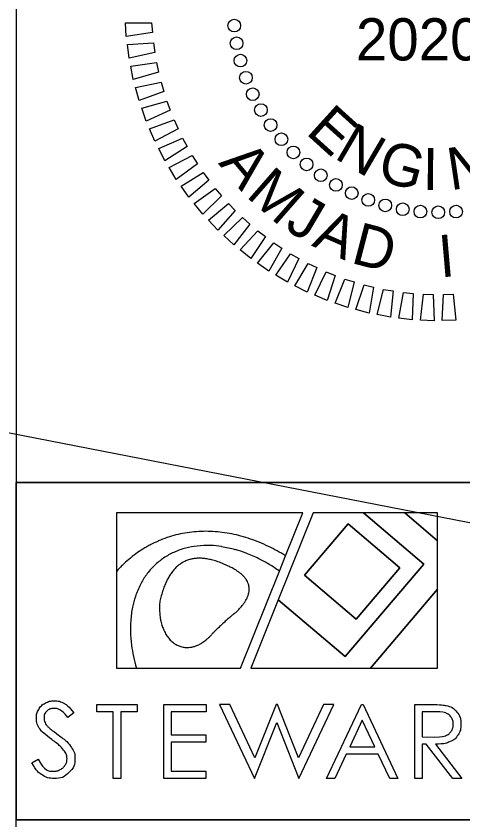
# Model space of a CAD drawing. Extents: x 1632447 to 1634147, y 883210 to 885181.
# Drawn here: x 1633913.8 to 1633966.7, y 884795.1 to 884890.3 of the extents above; entities that cross this region are included whole.
import ezdxf

# ---------------------------------------------------------------- set-up
doc = ezdxf.new("R2010")
doc.units = 0
for name, color, linetype in [('Default', 7, 'Continuous'), ('Scratch_Level_8', 7, 'Continuous'), ('Sheet PE Seal Cell', 7, 'Continuous'), ('Sheet Plan And Profile CELL', 7, 'Continuous'), ('Sheet Profile CELL', 7, 'Continuous')]:
    doc.layers.add(name, color=color, linetype=linetype)

msp = doc.modelspace()

# ---------------------------------------------------------------- linework, layer by layer
at = {"layer": 'Default'}
for p, q in [((1633947.786, 884831.455), (1633925.711, 884831.455)), ((1633925.711, 884831.455), (1633925.711, 884824.503)), ((1633949.016, 884831.455), (1633944.869, 884821.141)), ((1633945.732, 884826.348), (1633947.786, 884831.455)), ((1633954.969, 884831.455), (1633949.016, 884831.455)), ((1633954.969, 884831.455), (1633962.12, 884825.364)), ((1633959.863, 884831.455), (1633954.969, 884831.455)), ((1633962.12, 884825.364), (1633954.969, 884831.455)), ((1633963.748, 884831.455), (1633959.863, 884831.455)), ((1633959.863, 884831.455), (1633963.748, 884828.146)), ((1633963.748, 884828.146), (1633959.863, 884831.455)), ((1633963.748, 884828.146), (1633963.748, 884831.455)), ((1633931.724, 884828.517), (1633931.68, 884828.504)), ((1633938.234, 884829.128), (1633938.243, 884829.127)), ((1633930.659, 884828.114), (1633930.632, 884828.085)), ((1633938.146, 884827.422), (1633938.188, 884827.443)), ((1633943.718, 884827.467), (1633943.724, 884827.464)), ((1633963.748, 884822.381), (1633963.748, 884828.146)), ((1633945.004, 884824.537), (1633945.732, 884826.348)), ((1633925.711, 884824.503), (1633925.711, 884813.052)), ((1633940.386, 884813.052), (1633945.004, 884824.537)), ((1633962.12, 884825.364), (1633952.782, 884814.401)), ((1633952.782, 884814.401), (1633962.12, 884825.364)), ((1633954.102, 884818.861), (1633959.286, 884824.946)), ((1633963.748, 884822.381), (1633955.802, 884813.052)), ((1633955.802, 884813.052), (1633963.748, 884822.381)), ((1633963.748, 884813.052), (1633963.748, 884822.381)), ((1633944.869, 884821.141), (1633941.616, 884813.052)), ((1633952.782, 884814.401), (1633944.869, 884821.141)), ((1633944.869, 884821.141), (1633952.782, 884814.401)), ((1633925.711, 884813.052), (1633928.086, 884813.052)), ((1633928.086, 884813.052), (1633940.386, 884813.052)), ((1633941.616, 884813.052), (1633955.802, 884813.052)), ((1633955.802, 884813.052), (1633963.748, 884813.052)), ((1633939.126, 884808.723), (1633937.933, 884808.723)), ((1633937.933, 884808.723), (1633942.051, 884799.973)), ((1633942.102, 884802.417), (1633939.126, 884808.723)), ((1633944.626, 884808.723), (1633942.102, 884802.417)), ((1633944.796, 884808.723), (1633944.626, 884808.723)), ((1633947.275, 884802.417), (1633944.796, 884808.723)), ((1633950.251, 884808.723), (1633947.275, 884802.417)), ((1633947.313, 884799.973), (1633951.444, 884808.723)), ((1633951.444, 884808.723), (1633950.251, 884808.723)), ((1633942.051, 884799.973), (1633944.71, 884806.598)), ((1633944.71, 884806.598), (1633947.313, 884799.973)), ((1633913.826, 884771.558), (1633913.826, 884795.058)), ((1633913.826, 884795.058), (1634113.863, 884795.058)), ((1633913.826, 884771.558), (1633913.826, 884795.058)), ((1633913.826, 884795.058), (1634113.863, 884795.058))]:
    msp.add_line(p, q, dxfattribs=at)
for points in [[(1633913.813, 884835.058), (1634013.813, 884835.058), (1634013.813, 884795.058), (1633913.813, 884795.058)], [(1634013.813, 884835.058), (1633913.813, 884835.058), (1633913.813, 884795.058), (1634013.813, 884795.058)]]:
    msp.add_lwpolyline(points, close=True, dxfattribs=at)
for points in [[(1633947.991, 884824.066), (1633953.174, 884830.152), (1633959.286, 884824.946), (1633954.102, 884818.861), (1633947.991, 884824.066)], [(1633959.286, 884824.946), (1633953.174, 884830.152), (1633947.991, 884824.066), (1633954.102, 884818.861)], [(1633929.699, 884827.643), (1633929.775, 884827.686)], [(1633939.819, 884827.089), (1633939.775, 884827.068)], [(1633926.418, 884825.229), (1633926.358, 884825.187)], [(1633939.384, 884819.279), (1633939.264, 884819.179)], [(1633939.566, 884819.421), (1633939.486, 884819.36)], [(1633939.696, 884819.501), (1633939.626, 884819.463)], [(1633937.185, 884817.235), (1633937.085, 884817.132)], [(1633923.369, 884807.866), (1633923.369, 884808.723), (1633928.158, 884808.723), (1633928.158, 884807.866), (1633926.21, 884807.866), (1633926.21, 884799.973), (1633925.317, 884799.973), (1633925.317, 884807.866), (1633923.369, 884807.866)], [(1633931.325, 884808.723), (1633936.341, 884808.723), (1633936.341, 884807.866), (1633932.197, 884807.866), (1633932.197, 884805.124), (1633936.306, 884805.124), (1633936.306, 884804.267), (1633932.197, 884804.267), (1633932.197, 884800.83), (1633936.306, 884800.83), (1633936.306, 884799.973), (1633931.325, 884799.973), (1633931.325, 884808.723)], [(1633954.946, 884808.723), (1633959.027, 884799.973), (1633958.082, 884799.973), (1633956.708, 884802.857), (1633952.939, 884802.857), (1633951.578, 884799.973), (1633950.603, 884799.973), (1633954.734, 884808.723), (1633954.946, 884808.723)], [(1633961.041, 884808.723), (1633962.781, 884808.723)], [(1633963.488, 884804.033), (1633966.631, 884799.973), (1633965.549, 884799.973), (1633962.405, 884804.033), (1633961.913, 884804.033), (1633961.913, 884799.973), (1633961.041, 884799.973), (1633961.041, 884808.723)], [(1633920.645, 884807.727), (1633919.931, 884807.186)], [(1633961.913, 884807.866), (1633961.913, 884804.89), (1633963.419, 884804.878)], [(1633963.455, 884807.866), (1633961.913, 884807.866)], [(1633954.834, 884806.87), (1633953.337, 884803.7), (1633956.327, 884803.7), (1633954.834, 884806.87)], [(1633915.678, 884801.823), (1633916.422, 884802.269)]]:
    msp.add_lwpolyline(points, dxfattribs=at)
for centre, radius, start, end in [((1633936.259, 884814.687), 14.566, 91.0141, 95.33896), ((1633936.259, 884814.687), 14.566, 91.0141, 95.33896), ((1633936.275, 884813.805), 15.448, 86.81452, 91.0141), ((1633936.275, 884813.805), 15.448, 86.81452, 91.0141), ((1633936.203, 884815.137), 14.111, 108.6948, 113.13309), ((1633936.203, 884815.137), 14.111, 108.6948, 113.13309), ((1633936.06, 884815.704), 13.527, 104.17801, 108.6948), ((1633936.06, 884815.704), 13.527, 104.17801, 108.6948), ((1633936.203, 884815.137), 14.111, 99.74382, 104.17801), ((1633936.203, 884815.137), 14.111, 99.74382, 104.17801), ((1633936.235, 884814.952), 14.3, 95.33896, 99.74382), ((1633936.235, 884814.952), 14.3, 95.33896, 99.74382), ((1633936.275, 884813.805), 15.448, 82.68224, 86.81452), ((1633936.275, 884813.805), 15.448, 82.68224, 86.81452), ((1633936.078, 884812.334), 16.932, 78.75005, 82.68224), ((1633936.078, 884812.334), 16.932, 78.75005, 82.68224), ((1633936.192, 884812.909), 16.346, 74.86342, 78.75005), ((1633936.192, 884812.909), 16.346, 74.86342, 78.75005), ((1633935.582, 884810.654), 18.681, 71.22794, 74.86342), ((1633935.582, 884810.654), 18.681, 71.22794, 74.86342), ((1633935.955, 884811.751), 17.523, 67.61084, 71.22794), ((1633935.955, 884811.751), 17.523, 67.61084, 71.22794), ((1633936.399, 884815.042), 14.274, 117.64902, 121.98098), ((1633936.399, 884815.042), 14.274, 117.64902, 121.98098), ((1633935.782, 884816.031), 13.108, 113.13309, 117.64902), ((1633935.782, 884816.031), 13.108, 113.13309, 117.64902), ((1633936.154, 884818.904), 8.654, 95.97029, 104.98979), ((1633936.154, 884818.904), 8.654, 95.97029, 104.98979), ((1633936.498, 884815.62), 11.957, 88.29908, 95.97029), ((1633936.498, 884815.62), 11.957, 88.29908, 95.97029), ((1633936.549, 884817.368), 10.207, 80.76366, 88.29908), ((1633936.549, 884817.368), 10.207, 80.76366, 88.29908), ((1633935.612, 884811.838), 15.789, 74.71033, 80.76366), ((1633935.612, 884811.838), 15.789, 74.71033, 80.76366), ((1633934.784, 884808.909), 20.597, 64.27468, 67.61084), ((1633934.784, 884808.909), 20.597, 64.27468, 67.61084), ((1633935.138, 884809.66), 19.767, 60.92836, 64.27468), ((1633935.138, 884809.66), 19.767, 60.92836, 64.27468), ((1633936.843, 884814.591), 14.897, 126.38314, 130.51246), ((1633936.843, 884814.591), 14.897, 126.38314, 130.51246), ((1633935.782, 884816.031), 13.108, 121.98098, 126.38314), ((1633935.782, 884816.031), 13.108, 121.98098, 126.38314), ((1633935.825, 884819.411), 8.064, 114.2575, 124.17212), ((1633935.825, 884819.411), 8.064, 114.2575, 124.17212), ((1633936.302, 884818.352), 9.226, 104.98979, 114.2575), ((1633936.302, 884818.352), 9.226, 104.98979, 114.2575), ((1633936.604, 884815.327), 12.193, 68.58238, 74.71033), ((1633936.604, 884815.327), 12.193, 68.58238, 74.71033), ((1633933.756, 884808.066), 19.993, 63.79776, 68.58238), ((1633933.756, 884808.066), 19.993, 63.79776, 68.58238), ((1633935.138, 884809.66), 19.767, 57.5922, 60.92836), ((1633935.138, 884809.66), 19.767, 57.5922, 60.92836), ((1633936.183, 884815.363), 13.881, 130.51246, 134.70691), ((1633936.183, 884815.363), 13.881, 130.51246, 134.70691), ((1633935.78, 884819.477), 7.985, 124.17212, 134.18211), ((1633935.78, 884819.477), 7.985, 124.17212, 134.18211), ((1633935.409, 884822.325), 3.73, 119.02596, 126.10024), ((1633935.409, 884822.325), 3.73, 119.02596, 126.10024), ((1633935.377, 884822.382), 3.664, 111.82778, 119.02597), ((1633935.377, 884822.382), 3.664, 111.82778, 119.02597), ((1633935.415, 884822.287), 3.767, 104.72849, 111.82778), ((1633935.415, 884822.287), 3.767, 104.72849, 111.82778), ((1633935.45, 884822.157), 3.901, 97.90175, 104.7285), ((1633935.45, 884822.157), 3.901, 97.90175, 104.7285), ((1633935.531, 884821.573), 4.492, 91.53976, 97.90175), ((1633935.531, 884821.573), 4.492, 91.53976, 97.90175), ((1633935.54, 884821.227), 4.838, 85.68251, 91.53976), ((1633935.54, 884821.227), 4.838, 85.68251, 91.53976), ((1633935.452, 884820.06), 6.008, 80.42702, 85.68251), ((1633935.452, 884820.06), 6.008, 80.42702, 85.68251), ((1633935.356, 884819.488), 6.587, 75.69708, 80.42702), ((1633935.356, 884819.488), 6.587, 75.69708, 80.42702), ((1633934.887, 884817.652), 8.483, 71.52919, 75.69708), ((1633934.887, 884817.652), 8.483, 71.52919, 75.69708), ((1633934.243, 884815.724), 10.516, 67.79994, 71.52919), ((1633934.243, 884815.724), 10.516, 67.79994, 71.52919), ((1633935.035, 884817.664), 8.419, 63.63204, 67.79994), ((1633935.035, 884817.664), 8.419, 63.63204, 67.79994), ((1633935.612, 884811.838), 15.789, 58.77838, 63.79776), ((1633935.612, 884811.838), 15.789, 58.77838, 63.79776), ((1633936.399, 884815.042), 14.274, 134.70691, 138.48502), ((1633936.399, 884815.042), 14.274, 134.70691, 138.48502), ((1633936.363, 884818.877), 8.821, 134.18211, 143.7045), ((1633936.363, 884818.877), 8.821, 134.18211, 143.7045), ((1633936.491, 884821.24), 5.269, 139.15431, 144.89501), ((1633936.491, 884821.24), 5.269, 139.15431, 144.89501), ((1633935.811, 884821.829), 4.37, 132.84964, 139.15431), ((1633935.811, 884821.829), 4.37, 132.84964, 139.15431), ((1633935.625, 884822.029), 4.097, 126.10024, 132.84964), ((1633935.625, 884822.029), 4.097, 126.10024, 132.84964), ((1633936.28, 884819.098), 6.6, 63.90222, 67.78989), ((1633936.28, 884819.098), 6.6, 63.90222, 67.78989), ((1633935.372, 884817.245), 8.663, 60.50912, 63.90221), ((1633935.372, 884817.245), 8.663, 60.50912, 63.90221), ((1633936.356, 884818.985), 6.664, 56.62145, 60.50912), ((1633936.356, 884818.985), 6.664, 56.62145, 60.50912), ((1633937.341, 884820.479), 4.875, 52.07574, 56.62144), ((1633937.341, 884820.479), 4.875, 52.07574, 56.62144), ((1633934.79, 884810.481), 17.375, 53.99375, 58.77838), ((1633934.79, 884810.481), 17.375, 53.99375, 58.77838), ((1633935.827, 884819.27), 8.157, 143.7045, 153.10241), ((1633935.827, 884819.27), 8.157, 143.7045, 153.10241), ((1633938.254, 884820.174), 7.331, 150.09139, 154.70217), ((1633938.254, 884820.174), 7.331, 150.09139, 154.70217), ((1633936.903, 884820.951), 5.772, 144.89501, 150.09139), ((1633936.903, 884820.951), 5.772, 144.89501, 150.09139), ((1633937.699, 884820.939), 4.292, 46.84444, 52.07574), ((1633937.699, 884820.939), 4.292, 46.84444, 52.07574), ((1633938.452, 884821.742), 3.191, 40.77679, 46.84444), ((1633938.452, 884821.742), 3.191, 40.77679, 46.84444), ((1633938.721, 884821.974), 2.835, 33.89614, 40.77679), ((1633938.721, 884821.974), 2.835, 33.89614, 40.77679), ((1633939.199, 884822.295), 2.26, 26.18824, 33.89614), ((1633939.199, 884822.295), 2.26, 26.18824, 33.89614), ((1633938.421, 884817.954), 11.065, 153.10241, 161.16886), ((1633938.421, 884817.954), 11.065, 153.10241, 161.16886), ((1633941.157, 884818.991), 10.467, 158.82578, 162.45014), ((1633941.157, 884818.991), 10.467, 158.82578, 162.45014), ((1633938.937, 884819.851), 8.087, 154.70217, 158.82578), ((1633938.937, 884819.851), 8.087, 154.70217, 158.82578), ((1633939.344, 884822.367), 2.098, 17.85938, 26.18823), ((1633939.344, 884822.367), 2.098, 17.85938, 26.18823), ((1633939.506, 884822.419), 1.928, 9.17109, 17.85938), ((1633939.506, 884822.419), 1.928, 9.17109, 17.85938), ((1633939.5, 884822.418), 1.934, 0.50696, 9.17108), ((1633939.5, 884822.418), 1.934, 0.50696, 9.17108), ((1633943.529, 884818.241), 12.955, 162.45014, 165.69373), ((1633943.529, 884818.241), 12.955, 162.45014, 165.69373), ((1633938.554, 884822.599), 2.904, 337.85452, 344.63043), ((1633938.554, 884822.599), 2.904, 337.85452, 344.63043), ((1633939.135, 884822.439), 2.3, 344.63043, 352.24439), ((1633939.135, 884822.439), 2.3, 344.63043, 352.24439), ((1633939.308, 884822.416), 2.126, 352.24438, 0.50695), ((1633939.308, 884822.416), 2.126, 352.24438, 0.50695), ((1633936.85, 884818.49), 9.405, 161.16886, 169.12791), ((1633936.85, 884818.49), 9.405, 161.16886, 169.12791), ((1633938.393, 884820.135), 7.589, 174.9583, 179.11247), ((1633938.393, 884820.135), 7.589, 174.9583, 179.11247), ((1633941.03, 884818.878), 10.376, 165.69373, 169.31809), ((1633941.03, 884818.878), 10.376, 165.69373, 169.31809), ((1633936.705, 884823.604), 5.012, 322.29152, 326.75387), ((1633936.705, 884823.604), 5.012, 322.29152, 326.75387), ((1633937.207, 884823.275), 4.412, 326.75387, 331.89068), ((1633937.207, 884823.275), 4.412, 326.75387, 331.89068), ((1633938.211, 884822.739), 3.274, 331.89068, 337.85452), ((1633938.211, 884822.739), 3.274, 331.89068, 337.85452), ((1633941.9, 884817.52), 14.548, 169.1279, 175.52553), ((1633941.9, 884817.52), 14.548, 169.1279, 175.52553), ((1633937.586, 884820.147), 6.781, 179.11246, 183.50718), ((1633937.586, 884820.147), 6.781, 179.11246, 183.50718), ((1633939.551, 884820.268), 8.75, 183.50718, 187.66135), ((1633939.551, 884820.268), 8.75, 183.50718, 187.66135), ((1633935.218, 884824.594), 6.782, 311.32427, 315.14136), ((1633935.218, 884824.594), 6.782, 311.32427, 315.14136), ((1633933.72, 884826.084), 8.894, 315.14136, 318.47442), ((1633933.72, 884826.084), 8.894, 315.14136, 318.47442), ((1633935.252, 884824.728), 6.849, 318.47442, 322.29152), ((1633935.252, 884824.728), 6.849, 318.47442, 322.29152), ((1633936.22, 884819.819), 5.389, 187.66135, 192.95549), ((1633936.22, 884819.819), 5.389, 187.66135, 192.95549), ((1633960.882, 884794.188), 33.047, 131.95155, 132.39431), ((1633960.882, 884794.188), 33.047, 131.95155, 132.39431), ((1633956.951, 884798.561), 27.166, 131.46321, 131.95154), ((1633956.951, 884798.561), 27.166, 131.46321, 131.95154), ((1633952.344, 884803.776), 20.208, 130.86507, 131.46321), ((1633952.344, 884803.776), 20.208, 130.86507, 131.46321), ((1633949.463, 884807.105), 15.805, 130.18873, 130.86507), ((1633949.463, 884807.105), 15.805, 130.18873, 130.86507), ((1633945.41, 884811.903), 9.524, 129.24937, 130.18873), ((1633943.567, 884814.159), 6.611, 128.12185, 129.24938), ((1633943.567, 884814.159), 6.611, 128.12185, 129.24938), ((1633941.427, 884816.886), 3.145, 126.27417, 128.12186), ((1633940.539, 884818.097), 1.643, 123.71796, 126.27414), ((1633940.539, 884818.097), 1.643, 123.71796, 126.27414), ((1633939.765, 884819.256), 0.249, 118.06073, 123.718), ((1633940.222, 884818.399), 1.221, 115.50456, 118.0608), ((1633938.61, 884817.778), 11.248, 175.52553, 181.98726), ((1633938.61, 884817.778), 11.248, 175.52553, 181.98726), ((1633937.781, 884820.179), 6.991, 192.95549, 198.18402), ((1633937.781, 884820.179), 6.991, 192.95549, 198.18402), ((1633935.37, 884819.387), 4.454, 198.18403, 204.73613), ((1633935.37, 884819.387), 4.454, 198.18403, 204.73613), ((1633962.604, 884792.091), 35.754, 133.87638, 134.24875), ((1633962.604, 884792.091), 35.754, 133.87638, 134.24875), ((1633970.287, 884784.101), 46.838, 133.53679, 133.87639), ((1633970.287, 884784.101), 46.838, 133.53679, 133.87639), ((1633965.127, 884789.531), 39.348, 133.16627, 133.53679), ((1633965.127, 884789.531), 39.348, 133.16627, 133.53679), ((1633967.895, 884786.581), 43.393, 132.79754, 133.16627), ((1633967.895, 884786.581), 43.393, 132.79754, 133.16627), ((1633963.066, 884791.795), 36.286, 132.39431, 132.79754), ((1633963.066, 884791.795), 36.286, 132.39431, 132.79754), ((1633945.954, 884818.033), 18.595, 181.98726, 187.01165), ((1633945.954, 884818.033), 18.595, 181.98726, 187.01165), ((1633935.992, 884819.673), 5.138, 204.73614, 211.51028), ((1633935.992, 884819.673), 5.138, 204.73614, 211.51028), ((1633934.62, 884818.832), 3.529, 211.51028, 219.6861), ((1633934.62, 884818.832), 3.529, 211.51028, 219.6861), ((1633933.227, 884820.17), 4.896, 314.05681, 319.66219), ((1633933.227, 884820.17), 4.896, 314.05681, 319.66219), ((1633957.014, 884797.78), 27.779, 135.84186, 136.21617), ((1633957.014, 884797.78), 27.779, 135.84186, 136.21617), ((1633949.613, 884804.966), 17.464, 135.36978, 135.84187), ((1633960.405, 884794.313), 32.628, 134.99547, 135.36979), ((1633960.405, 884794.313), 32.628, 134.99547, 135.36979), ((1633957.082, 884797.637), 27.928, 134.59089, 134.99547), ((1633957.082, 884797.637), 27.928, 134.59089, 134.99547), ((1633967.206, 884787.367), 42.349, 134.24875, 134.59089), ((1633967.206, 884787.367), 42.349, 134.24875, 134.59089), ((1633934.691, 884818.891), 3.621, 219.6861, 228.4088), ((1633934.691, 884818.891), 3.621, 219.6861, 228.4088), ((1633934.202, 884818.34), 2.885, 228.4088, 238.184), ((1633934.202, 884818.34), 2.885, 228.4088, 238.184), ((1633934.061, 884818.78), 3.276, 295.379, 302.72034), ((1633934.061, 884818.78), 3.276, 295.379, 302.72034), ((1633932.797, 884820.749), 5.615, 302.72034, 308.32572), ((1633932.797, 884820.749), 5.615, 302.72034, 308.32572), ((1633933.375, 884820.018), 4.684, 308.32572, 314.05681), ((1633933.375, 884820.018), 4.684, 308.32572, 314.05681), ((1633942.242, 884817.576), 14.856, 187.01165, 192.25448), ((1633942.242, 884817.576), 14.856, 187.01165, 192.25448), ((1633934.11, 884818.192), 2.71, 238.184, 248.56848), ((1633934.11, 884818.192), 2.71, 238.184, 248.56848), ((1633934.117, 884818.208), 2.728, 248.56848, 258.91877), ((1633934.117, 884818.208), 2.728, 248.56848, 258.91877), ((1633934.06, 884817.917), 2.431, 258.91877, 269.50929), ((1633934.06, 884817.917), 2.431, 258.91877, 269.50929), ((1633934.066, 884818.647), 3.161, 269.50929, 278.79296), ((1633934.066, 884818.647), 3.161, 269.50929, 278.79296), ((1633934.141, 884818.163), 2.671, 278.79296, 288.01029), ((1633934.141, 884818.163), 2.671, 278.79296, 288.01029), ((1633933.675, 884819.594), 4.176, 288.01029, 295.379), ((1633933.675, 884819.594), 4.176, 288.01029, 295.379), ((1633943.531, 884817.856), 16.175, 192.25448, 197.27887), ((1633943.531, 884817.856), 16.175, 192.25448, 197.27887)]:
    msp.add_arc(centre, radius, start, end, dxfattribs=at)
for points in [[(1633916.422, 884802.269), (1633917.206, 884800.823), (1633918.234, 884800.823), (1633918.674, 884800.823), (1633919.061, 884801.028), (1633919.447, 884801.233), (1633919.649, 884801.578), (1633919.851, 884801.923), (1633919.851, 884802.309), (1633919.851, 884802.749), (1633919.554, 884803.171), (1633919.144, 884803.754), (1633918.056, 884804.575), (1633916.962, 884805.402), (1633916.695, 884805.77), (1633916.231, 884806.389), (1633916.231, 884807.109), (1633916.231, 884807.681), (1633916.504, 884808.151), (1633916.777, 884808.621), (1633917.273, 884808.892), (1633917.769, 884809.162), (1633918.352, 884809.162), (1633918.97, 884809.162), (1633919.507, 884808.856), (1633920.045, 884808.549), (1633920.645, 884807.727)], [(1633962.781, 884808.723), (1633964.236, 884808.723), (1633964.752, 884808.604), (1633965.53, 884808.425), (1633966.017, 884807.838), (1633966.504, 884807.251), (1633966.504, 884806.393), (1633966.504, 884805.678), (1633966.168, 884805.135), (1633965.833, 884804.593), (1633965.209, 884804.316), (1633964.586, 884804.039), (1633963.488, 884804.033)], [(1633919.931, 884807.186), (1633919.438, 884807.839), (1633919.09, 884808.047), (1633918.742, 884808.255), (1633918.332, 884808.255), (1633917.802, 884808.255), (1633917.467, 884807.934), (1633917.131, 884807.613), (1633917.131, 884807.144), (1633917.131, 884806.858), (1633917.25, 884806.591), (1633917.369, 884806.323), (1633917.684, 884806.008), (1633917.856, 884805.841), (1633918.813, 884805.134), (1633919.949, 884804.296), (1633920.371, 884803.642), (1633920.794, 884802.987), (1633920.794, 884802.328), (1633920.794, 884801.376), (1633920.072, 884800.675), (1633919.35, 884799.973), (1633918.316, 884799.973), (1633917.52, 884799.973), (1633916.872, 884800.398), (1633916.225, 884800.823), (1633915.678, 884801.823)], [(1633963.419, 884804.878), (1633964.294, 884804.878), (1633964.714, 884805.045), (1633965.134, 884805.211), (1633965.369, 884805.577), (1633965.604, 884805.943), (1633965.604, 884806.396), (1633965.604, 884806.836), (1633965.366, 884807.196), (1633965.128, 884807.556), (1633964.741, 884807.711), (1633964.354, 884807.866), (1633963.455, 884807.866)]]:
    msp.add_open_spline(points, degree=3, dxfattribs=at)
at = {"layer": 'Scratch_Level_8'}
msp.add_lwpolyline([(1632663.863, 883947.608), (1632663.863, 885084.125), (1634063.863, 884811.558), (1634013.863, 884541.527), (1634013.863, 883947.608)], close=True, dxfattribs=at)
at = {"layer": 'Sheet PE Seal Cell'}
for points in [[(1633929.962, 884888.369), (1633926.875, 884887.915), (1633926.791, 884889.529), (1633929.875, 884889.508)], [(1633930.25, 884886.014), (1633927.201, 884885.346), (1633927.005, 884886.95), (1633930.084, 884887.144)], [(1633930.701, 884883.684), (1633927.706, 884882.806), (1633927.399, 884884.392), (1633930.456, 884884.8)], [(1633931.313, 884881.392), (1633928.387, 884880.307), (1633927.97, 884881.868), (1633930.991, 884882.488)], [(1633932.084, 884879.148), (1633929.241, 884877.862), (1633928.716, 884879.39), (1633931.687, 884880.219)], [(1633933.01, 884876.964), (1633930.263, 884875.482), (1633929.633, 884876.97), (1633932.538, 884878.005)], [(1633934.086, 884874.849), (1633931.449, 884873.179), (1633930.716, 884874.62), (1633933.543, 884875.854)], [(1633935.306, 884872.815), (1633932.793, 884870.965), (1633931.961, 884872.351), (1633934.694, 884873.78)], [(1633936.666, 884870.87), (1633934.287, 884868.85), (1633933.361, 884870.174), (1633935.988, 884871.79)], [(1633938.157, 884869.026), (1633935.926, 884866.844), (1633934.909, 884868.1), (1633937.417, 884869.896)], [(1633939.774, 884867.289), (1633937.7, 884864.957), (1633936.599, 884866.14), (1633938.975, 884868.106)], [(1633941.508, 884865.67), (1633939.602, 884863.199), (1633938.421, 884864.302), (1633940.654, 884866.429)], [(1633943.351, 884864.176), (1633941.622, 884861.578), (1633940.366, 884862.596), (1633942.446, 884864.873)], [(1633945.294, 884862.814), (1633943.75, 884860.101), (1633942.426, 884861.029), (1633944.342, 884863.446)], [(1633947.326, 884861.59), (1633945.976, 884858.777), (1633944.591, 884859.61), (1633946.333, 884862.155)], [(1633949.44, 884860.512), (1633948.288, 884857.611), (1633946.849, 884858.345), (1633948.41, 884861.006)], [(1633951.623, 884859.583), (1633950.677, 884856.609), (1633949.189, 884857.242), (1633950.561, 884860.004)], [(1633953.866, 884858.809), (1633953.129, 884855.777), (1633951.601, 884856.303), (1633952.777, 884859.155)], [(1633956.157, 884858.194), (1633955.634, 884855.117), (1633954.073, 884855.536), (1633955.047, 884858.463)], [(1633958.485, 884857.739), (1633958.178, 884854.634), (1633956.592, 884854.943), (1633957.359, 884857.93)], [(1633960.84, 884857.449), (1633960.75, 884854.329), (1633959.146, 884854.527), (1633959.703, 884857.561)], [(1633963.209, 884857.323), (1633963.337, 884854.205), (1633961.723, 884854.29), (1633962.067, 884857.355)], [(1633965.581, 884857.363), (1633965.927, 884854.261), (1633964.311, 884854.233), (1633964.44, 884857.315)]]:
    msp.add_lwpolyline(points, close=True, dxfattribs=at)
for centre in [(1633939.668, 884889.194), (1633939.944, 884887.097), (1633940.402, 884885.032), (1633941.038, 884883.014), (1633941.848, 884881.059), (1633942.825, 884879.183), (1633943.961, 884877.399), (1633945.249, 884875.72), (1633946.678, 884874.161), (1633948.238, 884872.731), (1633949.917, 884871.444), (1633951.701, 884870.307), (1633953.577, 884869.33), (1633955.532, 884868.52), (1633957.549, 884867.884), (1633959.615, 884867.426), (1633961.712, 884867.15), (1633963.826, 884867.058), (1633965.939, 884867.15)]:
    msp.add_circle(centre, 0.75, dxfattribs=at)
at = {"layer": 'Sheet Plan And Profile CELL'}
for p, q in [((1633913.813, 884835.058), (1633913.826, 884795.058)), ((1633913.826, 884795.058), (1634113.863, 884795.058))]:
    msp.add_line(p, q, dxfattribs=at)
at = {"layer": 'Sheet Profile CELL'}
msp.add_lwpolyline([(1633913.813, 884947.558), (1633913.813, 884835.058), (1634113.863, 884835.058)], dxfattribs=at)

# ---------------------------------------------------------------- texts
at = {"layer": 'Sheet PE Seal Cell'}
for s, rotation, p in [('20204', 360, (1633954.078, 884885.058)), ('E', 317.85062, (1633948.016, 884876.45)), ('N', 329.61286, (1633951.377, 884873.539)), ('G', 344.66291, (1633956.418, 884870.916)), ('N', 8.46841, (1633965.279, 884869.661)), ('A', 309.74694, (1633937.709, 884872.862)), ('I', 359.71297, (1633961.967, 884869.692)), ('M', 318.79443, (1633940.934, 884868.985)), ('J', 329.50053, (1633945.48, 884865.121)), ('A', 336.33844, (1633948.728, 884863.123)), ('D', 345.38593, (1633953.348, 884861.099)), ('I', 4.95842, (1633964.074, 884859.335))]:
    msp.add_text(s, height=5, rotation=rotation, dxfattribs=at).set_placement(p)

doc.saveas('drawing.dxf')
